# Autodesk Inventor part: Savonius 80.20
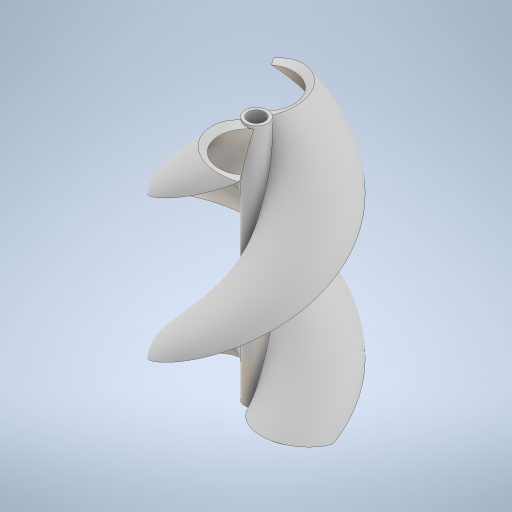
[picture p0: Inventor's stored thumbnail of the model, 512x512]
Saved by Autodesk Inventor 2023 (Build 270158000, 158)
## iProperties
Created: 2025-05
Part Number: Savonius 80.20
Material: Generic
Document SubType Name: Modeling
Designer: Brecht.Carpentier
Density: 1 g/cm^3
Appearance: Default
Author: Brecht.Carpentier
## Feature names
1. Extrusion1
2. Extrusion2
## Parameters: d1 = 85 mm, d2 = 25 mm, d3 = 0, d4 = 5.8 mm, d5 = 8 mm, d8 = 86 mm, d9 = 0, d12 = 0, d13 = 0, d14 = 3 mm, d15 = 1 mm, d18 = 3 mm, d19 = 1 mm, d20 = 0, d21 = 0
